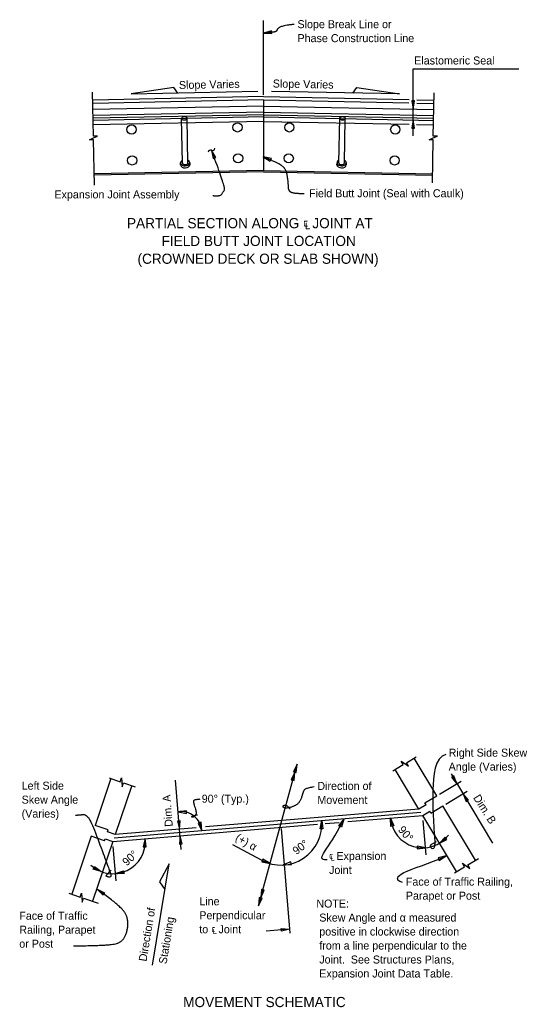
# Model space of a CAD drawing. Extents: x 0 to 9.02, y -1.12 to 4.98.
# Drawn here: x 3.193 to 4.79, y 1.876 to 4.984 of the extents above; entities that cross this region are included whole.
import ezdxf

# ---------------------------------------------------------------- set-up
doc = ezdxf.new("R2010")
doc.units = 0
for name, color, linetype in [('Dimension', 7, 'Continuous'), ('Miscellaneous', 7, 'Continuous'), ('SteelGirder', 7, 'Continuous'), ('SteelGirder_h', 7, 'Continuous'), ('SupstrConc', 7, 'Continuous'), ('TextStructures', 7, 'Continuous')]:
    doc.layers.add(name, color=color, linetype=linetype)

msp = doc.modelspace()

# ---------------------------------------------------------------- linework, layer by layer
at = {"layer": 'Dimension'}
for p, q in [((3.9593, 4.7475), (3.9593, 4.9812)), ((4.4304, 4.8287), (4.7632, 4.8287)), ((4.4304, 4.7025), (4.4304, 4.8287)), ((4.4304, 4.6682), (4.4304, 4.7025)), ((4.4304, 4.6186), (4.4304, 4.6682)), ((3.944, 2.1947), (4.0651, 2.6405)), ((3.701, 2.3719), (3.6827, 2.59)), ((4.5139, 2.5466), (4.5818, 2.5873)), ((4.55, 2.6099), (4.6807, 2.3921)), ((4.533, 2.5148), (4.6008, 2.5555)), ((4.4712, 2.3552), (4.4621, 2.4638)), ((4.0153, 2.4381), (4.0429, 2.1084)), ((3.4962, 2.2734), (3.4871, 2.382)), ((3.9533, 2.3384), (3.8633, 2.3863)), ((4.0418, 2.1216), (3.9676, 2.1154))]:
    msp.add_line(p, q, dxfattribs=at)
for points in [[(3.9593, 4.9415), (3.9857, 4.9402), (3.9846, 4.949)], [(4.4304, 4.7025), (4.4348, 4.7285), (4.4259, 4.7285)], [(4.4304, 4.6682), (4.426, 4.6422), (4.4348, 4.6422)], [(3.7962, 4.5726), (3.8013, 4.5467), (3.8095, 4.5499)], [(3.9585, 4.5522), (3.981, 4.5383), (3.9843, 4.5465)], [(4.0583, 2.6154), (4.0472, 2.5914), (4.0557, 2.5891)], [(4.0651, 2.6405), (4.054, 2.6166), (4.0626, 2.6143)], [(4.5684, 2.5793), (4.5588, 2.6039), (4.5512, 2.5993)], [(4.5875, 2.5475), (4.5971, 2.5229), (4.6046, 2.5275)], [(3.691, 2.4907), (3.7169, 2.4854), (3.7172, 2.4942)], [(3.6956, 2.4362), (3.6978, 2.4626), (3.689, 2.4618)], [(3.7653, 2.4314), (3.763, 2.4577), (3.7545, 2.4555)], [(4.1376, 2.4375), (4.1429, 2.4634), (4.1464, 2.4372)], [(4.1967, 2.4461), (4.2124, 2.4674), (4.2046, 2.4422)], [(4.3607, 2.4447), (4.3591, 2.4711), (4.3693, 2.4468)], [(3.5903, 2.3801), (3.5875, 2.4063), (3.5815, 2.3806)], [(3.6973, 2.4156), (3.6951, 2.3892), (3.7039, 2.39)], [(4.5133, 2.3921), (4.5369, 2.404), (4.5316, 2.4111)], [(4.4693, 2.3779), (4.4434, 2.3828), (4.4432, 2.374)], [(3.9801, 2.3278), (3.9576, 2.3416), (3.9543, 2.3335)], [(4.0211, 2.3234), (4.0474, 2.3253), (4.0454, 2.3338)], [(4.5348, 2.3518), (4.509, 2.3459), (4.5124, 2.3378)], [(3.4486, 2.3028), (3.4234, 2.3106), (3.4274, 2.3184)], [(3.4943, 2.2961), (3.5191, 2.3052), (3.5207, 2.2966)], [(3.4547, 2.2287), (3.4358, 2.2472), (3.4597, 2.2359)], [(3.9508, 2.2198), (3.9619, 2.2438), (3.9534, 2.2461)], [(3.944, 2.1947), (3.955, 2.2187), (3.9465, 2.221)], [(4.0155, 2.1238), (4.0418, 2.1216), (4.0162, 2.115)]]:
    msp.add_lwpolyline(points, close=True, dxfattribs=at)
for points in [[(3.4278, 4.4627), (3.4249, 4.6058), (3.412, 4.6056), (3.4248, 4.6114), (3.4376, 4.6173), (3.4247, 4.6171), (3.4219, 4.7552)], [(3.6901, 4.7528), (3.678, 4.7703), (3.5435, 4.7503), (3.9414, 4.7583)], [(4.2408, 4.7526), (4.253, 4.7701), (4.3874, 4.7501), (3.9851, 4.7581)], [(4.491, 4.4701), (4.4938, 4.6058), (4.4809, 4.6061), (4.4939, 4.6114), (4.5069, 4.6168), (4.494, 4.6171), (4.4967, 4.7538)], [(4.367, 2.6199), (4.3996, 2.6395), (4.3929, 2.6506), (4.4044, 2.6424), (4.4159, 2.6342), (4.4092, 2.6453), (4.4399, 2.6637)], [(3.4739, 2.5975), (3.5089, 2.5856), (3.513, 2.5978), (3.5142, 2.5838), (3.5154, 2.5697), (3.5195, 2.582), (3.5554, 2.5698)], [(4.5603, 2.2987), (4.5925, 2.318), (4.5858, 2.3291), (4.5973, 2.3209), (4.6087, 2.3128), (4.6021, 2.3238), (4.6361, 2.3442)], [(3.61, 2.0085), (3.6631, 2.3269), (3.6328, 2.2708), (3.6496, 2.2459)], [(3.3466, 2.2349), (3.383, 2.2225), (3.3871, 2.2348), (3.3883, 2.2207), (3.3894, 2.2067), (3.3936, 2.2189), (3.4393, 2.2034)]]:
    msp.add_lwpolyline(points, dxfattribs=at)
for centre, radius, start, end in [((3.793, 4.5659), 0.00745, 64.8627, 176.5899), ((3.7993, 4.5794), 0.00745, 244.8627, 356.5899), ((3.7004, 2.4262), 0.0652, 4.5549, 98.2515), ((4.014, 2.4525), 0.1293, 241.9734, 4.7968), ((4.4608, 2.4796), 0.1021, 184.7968, 322.3219), ((3.4858, 2.3978), 0.1021, 227.2717, 4.7968)]:
    msp.add_arc(centre, radius, start, end, dxfattribs=at)
for points, degree in [([(4.0559, 4.9689), (4.0187, 4.9653), (4.0015, 4.9533), (4.001, 4.9454), (3.9758, 4.9434), (3.9593, 4.9414)], 2), ([(3.7997, 4.43), (3.8145, 4.4294), (3.8266, 4.4307), (3.832, 4.4415), (3.8418, 4.4519), (3.7962, 4.5727)], 2), ([(4.088, 4.4358), (4.054, 4.4358), (4.0379, 4.4453), (4.0379, 4.4716), (4.0313, 4.5134), (4.0057, 4.5331), (3.9585, 4.5522)], 2), ([(4.5337, 2.6716), (4.4974, 2.6626), (4.491, 2.5412), (4.4931, 2.4705), (4.5008, 2.3786), (4.494, 2.3745), (4.4878, 2.3739), (4.4803, 2.3863), (4.5038, 2.3971)], 3), ([(4.1186, 2.5693), (4.091, 2.5647), (4.0842, 2.554), (4.0766, 2.5254), (4.0602, 2.5093), (4.0304, 2.5009), (4.0194, 2.5061), (4.0238, 2.5129), (4.0357, 2.5103), (4.043, 2.4992)], 2), ([(3.7597, 2.5301), (3.7405, 2.5291), (3.7383, 2.5211), (3.7491, 2.4893), (3.7447, 2.4786), (3.7402, 2.4741), (3.7339, 2.4736), (3.7336, 2.4774), (3.7518, 2.4815)], 2), ([(3.3679, 2.4801), (3.3854, 2.4816), (3.4093, 2.4836), (3.474, 2.3089), (3.4818, 2.2859), (3.4711, 2.285), (3.461, 2.2894), (3.48, 2.3069)], 2), ([(4.1604, 2.3397), (4.1553, 2.3397), (4.1392, 2.3382), (4.1463, 2.3616), (4.1832, 2.4096), (4.2124, 2.4674)], 3), ([(4.3975, 2.2685), (4.3941, 2.2709), (4.3854, 2.2676), (4.3712, 2.2965), (4.4805, 2.3275), (4.5348, 2.3518)], 3), ([(3.3616, 2.0692), (3.4644, 2.0692), (3.5206, 2.0808), (3.5376, 2.1434), (3.5164, 2.1911), (3.4358, 2.2472)], 2)]:
    msp.add_open_spline(points, degree=degree, dxfattribs=at)
at = {"layer": 'Miscellaneous'}
for p, q in [((4.3375, 4.7036), (4.3376, 4.7039)), ((3.4894, 2.4085), (4.4548, 2.4895))]:
    msp.add_line(p, q, dxfattribs=at)
for points in [[(3.9593, 4.7119), (3.4228, 4.7012)], [(3.9593, 4.7119), (4.4959, 4.7012)], [(3.9599, 4.6844), (3.4233, 4.6737)], [(3.96, 4.6776), (3.4235, 4.6669)], [(3.9593, 4.6844), (4.4953, 4.6737)], [(3.9593, 4.6776), (4.4952, 4.6669)]]:
    msp.add_lwpolyline(points, dxfattribs=at)
at = {"layer": 'SteelGirder'}
for p, q in [((3.9593, 4.7311), (3.9593, 4.7119)), ((3.9593, 4.6776), (3.9593, 4.5089)), ((3.4931, 2.4193), (3.4687, 2.4275))]:
    msp.add_line(p, q, dxfattribs=at)
for points in [[(3.9593, 4.7311), (3.4224, 4.7204)], [(3.9593, 4.7311), (4.4174, 4.722)], [(4.4422, 4.7215), (4.4963, 4.7204)], [(3.9593, 4.5089), (3.4269, 4.4982)], [(3.9593, 4.5089), (4.4918, 4.4982)], [(4.4489, 2.4995), (3.777, 2.4431)], [(4.2245, 2.4598), (4.4608, 2.4796), (4.4829, 2.4929)], [(4.471, 2.5127), (4.4489, 2.4995)], [(4.1541, 2.4539), (4.1972, 2.4575)], [(3.4614, 2.4061), (3.4858, 2.3978), (4.1297, 2.4518)], [(3.7475, 2.4406), (3.4931, 2.4193)]]:
    msp.add_lwpolyline(points, dxfattribs=at)
at = {"layer": 'SteelGirder_h'}
for p, q in [((3.9593, 4.7119), (3.9593, 4.6776)), ((3.7046, 4.5332), (3.7018, 4.6729)), ((3.7219, 4.5336), (3.7191, 4.6733)), ((4.1968, 4.5336), (4.1996, 4.6733)), ((4.2141, 4.5332), (4.2169, 4.6729)), ((3.6989, 4.5265), (3.6987, 4.5331)), ((3.7278, 4.5337), (3.7279, 4.5271)), ((4.1908, 4.5271), (4.1909, 4.5337)), ((4.22, 4.5331), (4.2198, 4.5265))]:
    msp.add_line(p, q, dxfattribs=at)
for points in [[(3.9593, 4.6925), (3.4232, 4.6818)], [(3.9593, 4.6637), (3.4238, 4.653)], [(3.9593, 4.6925), (4.4955, 4.6818)], [(3.9593, 4.6637), (4.4175, 4.6545)], [(4.4411, 4.6541), (4.4949, 4.653)]]:
    msp.add_lwpolyline(points, dxfattribs=at)
for centre in [(3.5445, 4.638), (3.8777, 4.6447), (4.041, 4.6447), (4.3742, 4.638), (3.5464, 4.5408), (3.8797, 4.5475), (4.039, 4.5475), (4.3723, 4.5408)]:
    msp.add_circle(centre, 0.0145, dxfattribs=at)
for centre, major_axis in [((3.7105, 4.6731), (0.00868, 0.00017)), ((4.2082, 4.6731), (0.00868, -0.00017))]:
    msp.add_ellipse(centre, major_axis=major_axis, ratio=0.654774, dxfattribs=at)
for centre, major_axis, ratio, start_param, end_param in [((3.7132, 4.5334), (0.0145, 0.0003), 0.654766, 2.211147, 7.21363), ((4.2054, 4.5334), (0.0145, -0.0003), 0.654766, 2.211147, 7.21363), ((3.7134, 4.5268), (0.0145, 0.0003), 0.654766, 3.141593, 6.283185), ((3.7132, 4.5334), (0.00868, 0.00017), 0.654774, 3.1416, 6.283178), ((4.2053, 4.5268), (0.0145, -0.0003), 0.654766, 3.141593, 6.283185), ((4.2054, 4.5334), (0.00868, -0.00017), 0.654774, 3.1416, 6.283178)]:
    msp.add_ellipse(centre, major_axis=major_axis, ratio=ratio, start_param=start_param, end_param=end_param, dxfattribs=at)
at = {"layer": 'SupstrConc'}
for p, q in [((4.5049, 2.5411), (4.4336, 2.6599)), ((4.4489, 2.4995), (4.3741, 2.6242)), ((3.4795, 2.5956), (3.4295, 2.4481)), ((3.5453, 2.5732), (3.4931, 2.4193)), ((4.4674, 2.5186), (4.5049, 2.5411)), ((4.471, 2.5127), (4.4674, 2.5186)), ((4.4864, 2.4869), (4.4829, 2.4929)), ((4.4864, 2.4869), (4.5239, 2.5094)), ((4.6265, 2.3385), (4.5239, 2.5094)), ((4.5669, 2.3027), (4.4608, 2.4796)), ((3.4709, 2.4341), (3.4295, 2.4481)), ((3.4687, 2.4275), (3.4709, 2.4341)), ((3.4178, 2.4136), (3.3561, 2.2317)), ((3.4592, 2.3995), (3.4178, 2.4136)), ((3.4858, 2.3978), (3.4218, 2.2093)), ((3.4592, 2.3995), (3.4614, 2.4061))]:
    msp.add_line(p, q, dxfattribs=at)
for points in [[(3.9593, 4.7415), (3.4222, 4.7308)], [(3.9593, 4.7415), (4.4176, 4.7324)], [(4.4424, 4.7319), (4.4965, 4.7308)], [(3.9593, 4.5054), (3.4271, 4.4948)], [(3.9593, 4.5054), (4.4916, 4.4948)]]:
    msp.add_lwpolyline(points, dxfattribs=at)

# ---------------------------------------------------------------- texts
at = {"layer": 'TextStructures'}
for s, height, p in [('Slope Break Line or', 0.0252, (4.0666, 4.957)), ('Phase Construction Line', 0.0252, (4.0666, 4.913)), ('Elastomeric Seal', 0.0252, (4.4338, 4.8427)), ('Expansion Joint Assembly', 0.0252, (3.3017, 4.4212)), ('Field Butt Joint (Seal with Caulk)', 0.0252, (4.1029, 4.4249)), ('PARTIAL SECTION ALONG ℄ JOINT AT', 0.032, (3.5301, 4.3274)), ('FIELD BUTT JOINT LOCATION', 0.032, (3.639, 4.2714)), ('(CROWNED DECK OR SLAB SHOWN)', 0.032, (3.5633, 4.2154)), ('Right Side Skew ', 0.0252, (4.5422, 2.6643)), ('Angle (Varies)', 0.0252, (4.5422, 2.6203)), ('Left Side ', 0.0252, (3.1986, 2.5604)), ('Direction of ', 0.0252, (4.1291, 2.5596)), ('Skew Angle ', 0.0252, (3.1986, 2.5164)), ('90° (Typ.) ', 0.0252, (3.7653, 2.5194)), ('Movement', 0.0252, (4.1291, 2.5156)), ('(Varies)', 0.0252, (3.1986, 2.4724)), ('℄ Expansion ', 0.0252, (4.1659, 2.3392)), ('Joint', 0.0252, (4.1659, 2.2952)), ('Face of Traffic Railing, ', 0.0252, (4.4075, 2.2583)), ('Parapet or Post', 0.0252, (4.4075, 2.2143)), ('Line ', 0.0252, (3.7576, 2.1966)), ('NOTE:  ', 0.0252, (4.1258, 2.1893)), ('Face of Traffic', 0.0252, (3.1912, 2.1511)), ('Perpendicular ', 0.0252, (3.7576, 2.1526)), (' Skew Angle and α measured ', 0.0252, (4.1258, 2.1453)), ('Railing, Parapet', 0.0252, (3.1912, 2.1071)), ('to ℄ Joint', 0.0252, (3.7576, 2.1086)), (' positive in clockwise direction ', 0.0252, (4.1258, 2.1013)), ('or Post', 0.0252, (3.1912, 2.0631)), (' from a line perpendicular to the ', 0.0252, (4.1258, 2.0573)), (' Joint.  See Structures Plans, ', 0.0252, (4.1258, 2.0133)), (' Expansion Joint Data Table.', 0.0252, (4.1258, 1.9693)), ('MOVEMENT SCHEMATIC', 0.032, (3.7071, 1.8761))]:
    msp.add_text(s, height=height, dxfattribs=at).set_placement(p)
for s, rotation, p in [('Slope Varies', 1.1457, (3.6938, 4.7653)), ('Slope Varies', 358.8543, (3.9887, 4.7704)), ('Dim. A', 94.3896, (3.6744, 2.4445)), ('Dim. B', 302.1391, (4.6184, 2.5351)), ('90°', 309.7565, (4.3813, 2.4334)), ('(+) α', 330.5011, (3.8685, 2.4021)), ('90°', 37.1776, (4.063, 2.3541)), ('90°', 43.1571, (3.5296, 2.3189)), ('Direction of', 80.5333, (3.5914, 2.0184)), ('Stationing', 80.5333, (3.6544, 2.0103))]:
    msp.add_text(s, height=0.0252, rotation=rotation, dxfattribs=at).set_placement(p)

doc.saveas('drawing.dxf')
